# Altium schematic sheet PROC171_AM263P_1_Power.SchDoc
size 431 x 279 mm; Date: Not shown in title block; ApprovedBy: Not shown in title block; CheckedBy: Not shown in title block; Author: Not shown in title block; CompanyName: Not shown in title block; Engineer: Not shown in title block; Organization: Not shown in title block; Address1: Not shown in title block; Address2: Not shown in title block; Address3: Not shown in title block; Address4: Not shown in title block; DocumentNumber: 4; Revision: Use project parameter SCH_Rev; SheetNumber: 4; SheetTotal: 26; PageSetup: Record=PageOptions¦CenterHorizontal=True¦CenterVertical=True¦PrintScale=1.00¦XCorrection=1.00¦YCorrection=1.00¦PrintKind=0¦BorderSize=5000000¦LeftOffset=0¦BottomOffset=0¦Orientation=2¦PaperLength=1000¦PaperWidth=1000¦Scale=100¦PaperSource=15¦PrintQuality=600¦MediaType=1¦DitherType=10¦PaperKind=Letter¦PrintScaleMode=1
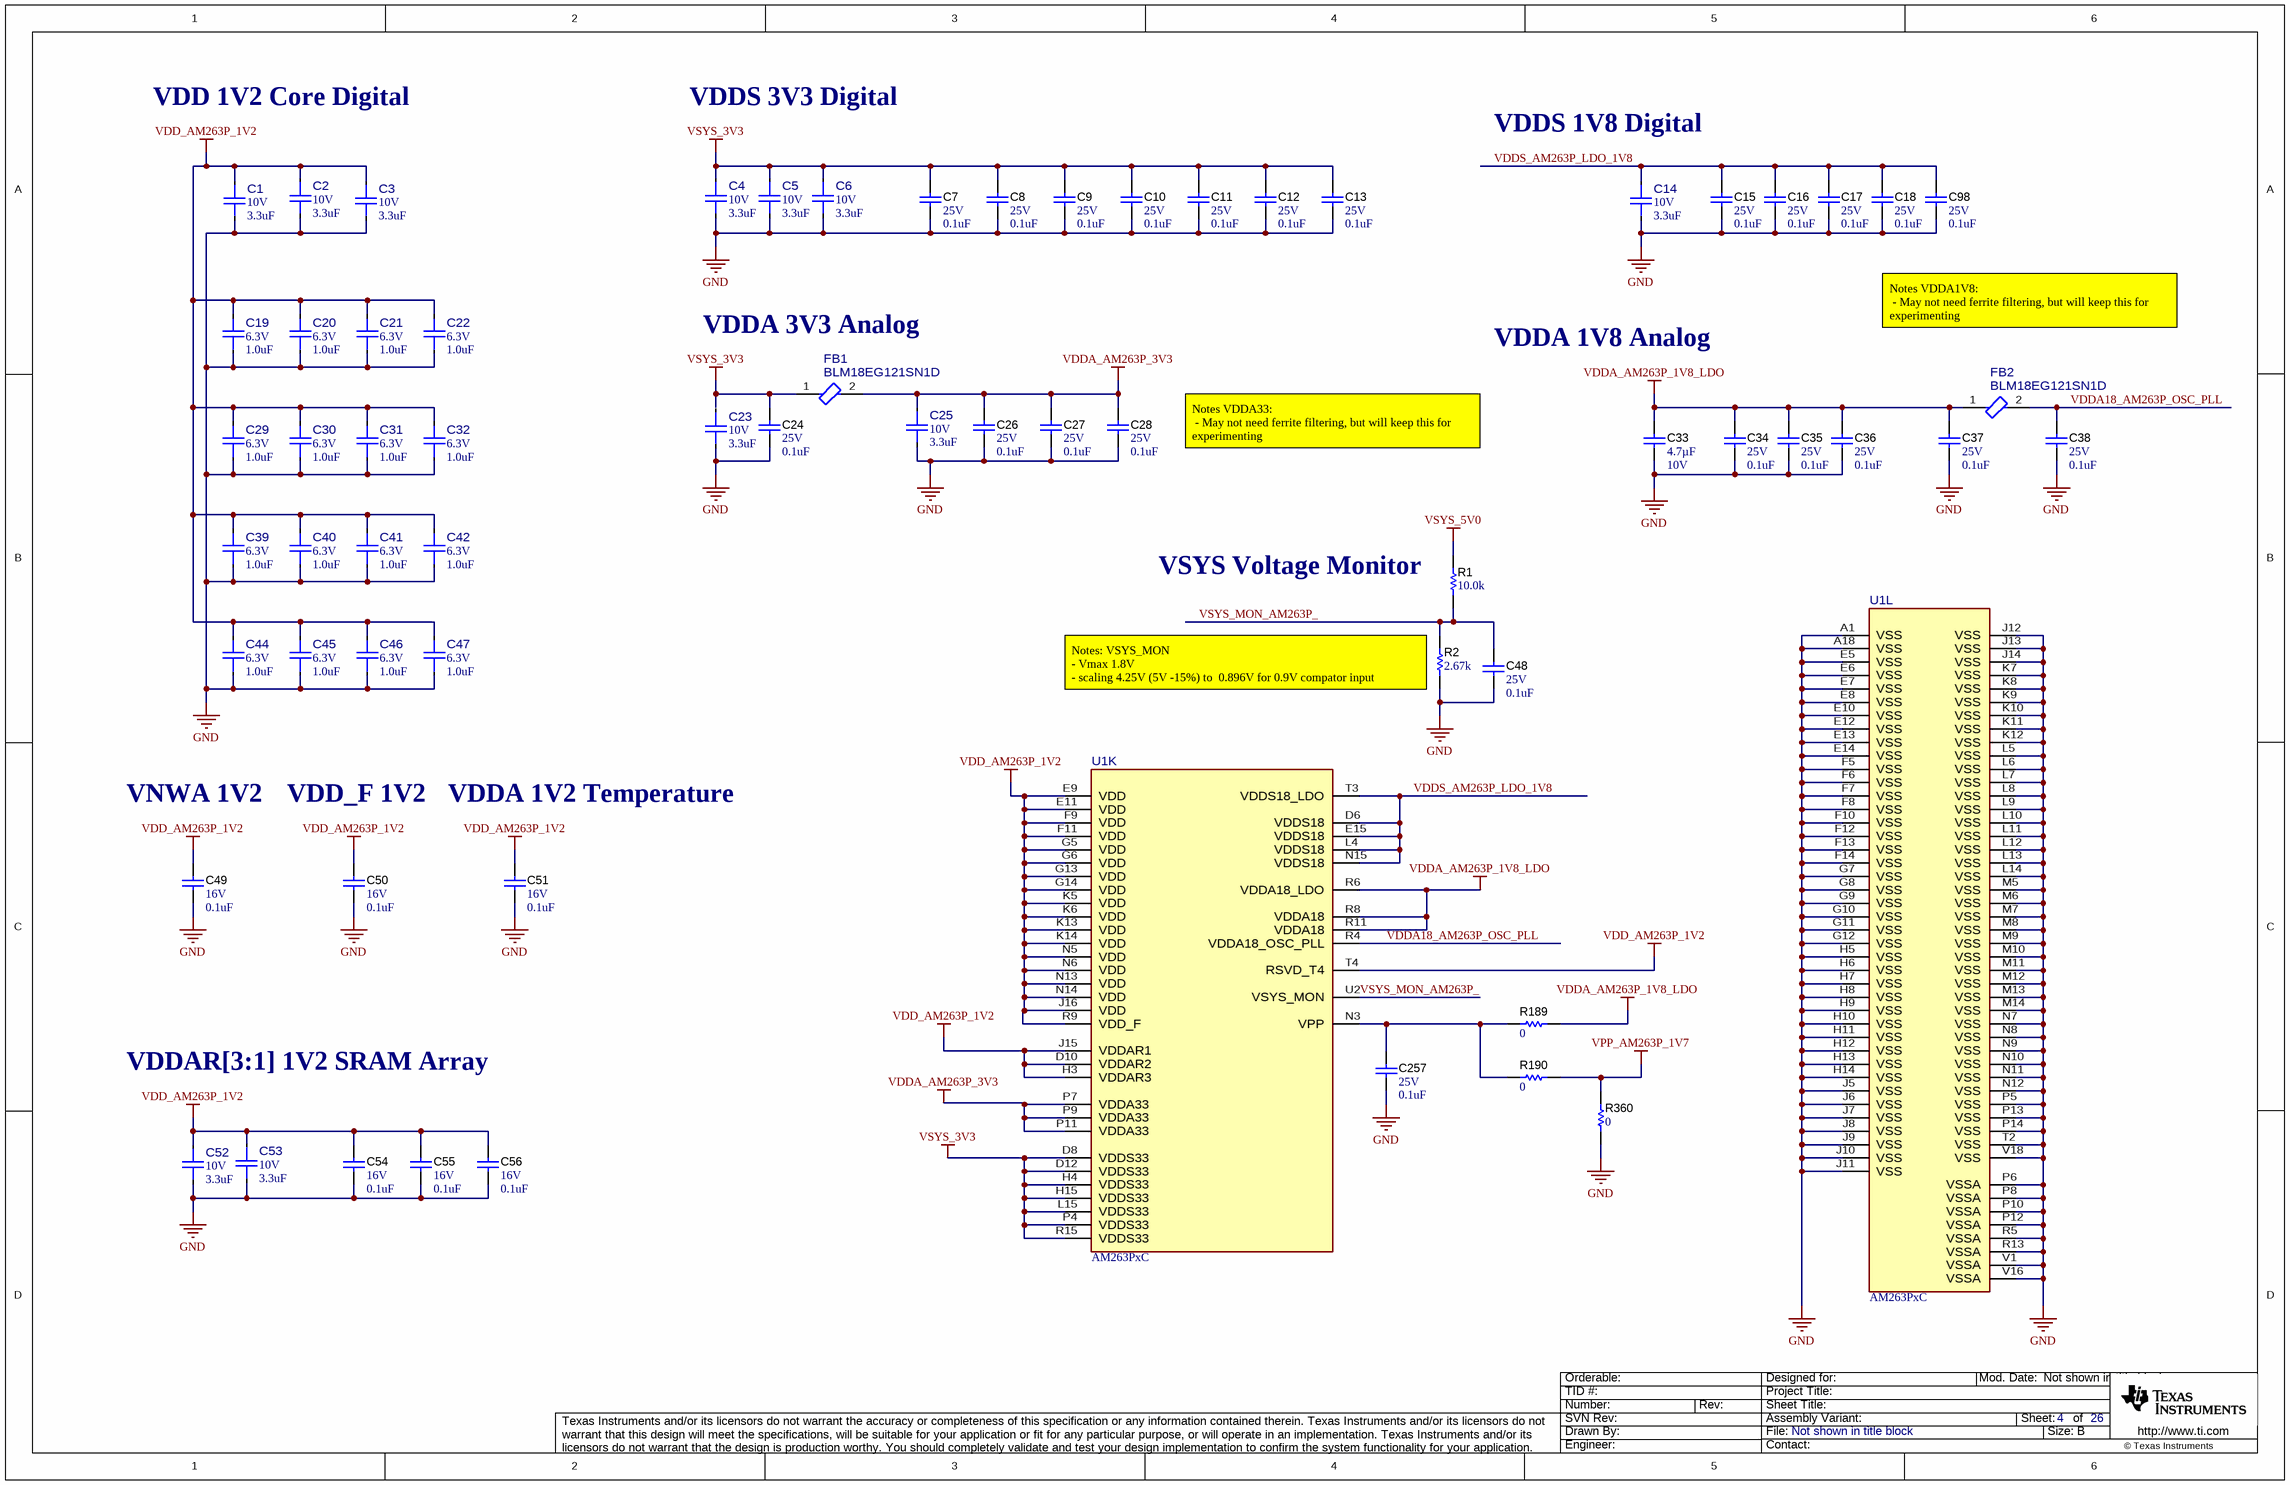
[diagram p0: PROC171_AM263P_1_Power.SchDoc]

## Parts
C1  VDC_V: 10V  ValueDisplayed: 3.3uF  [FP-CL10A335KP8NNNC_0603-MFG]  (hidden comment: CL10A335KP8NNNC)
C2  VDC_V: 10V  ValueDisplayed: 3.3uF  [FP-CL10A335KP8NNNC_0603-MFG]  (hidden comment: CL10A335KP8NNNC)
C3  VDC_V: 10V  ValueDisplayed: 3.3uF  [FP-CL10A335KP8NNNC_0603-MFG]  (hidden comment: CL10A335KP8NNNC)
C4  VDC_V: 10V  ValueDisplayed: 3.3uF  [FP-CL10A335KP8NNNC_0603-MFG]  (hidden comment: CL10A335KP8NNNC)
C5  VDC_V: 10V  ValueDisplayed: 3.3uF  [FP-CL10A335KP8NNNC_0603-MFG]  (hidden comment: CL10A335KP8NNNC)
C6  VDC_V: 10V  ValueDisplayed: 3.3uF  [FP-CL10A335KP8NNNC_0603-MFG]  (hidden comment: CL10A335KP8NNNC)
C7  VDC_V: 25V  ValueDisplayed: 0.1uF  [0402]  (hidden comment: GRM155R71E104KE14D)
C8  VDC_V: 25V  ValueDisplayed: 0.1uF  [0402]  (hidden comment: GRM155R71E104KE14D)
C9  VDC_V: 25V  ValueDisplayed: 0.1uF  [0402]  (hidden comment: GRM155R71E104KE14D)
C10  VDC_V: 25V  ValueDisplayed: 0.1uF  [0402]  (hidden comment: GRM155R71E104KE14D)
C11  VDC_V: 25V  ValueDisplayed: 0.1uF  [0402]  (hidden comment: GRM155R71E104KE14D)
C12  VDC_V: 25V  ValueDisplayed: 0.1uF  [0402]  (hidden comment: GRM155R71E104KE14D)
C13  VDC_V: 25V  ValueDisplayed: 0.1uF  [0402]  (hidden comment: GRM155R71E104KE14D)
C14  VDC_V: 10V  ValueDisplayed: 3.3uF  [FP-CL10A335KP8NNNC_0603-MFG]  (hidden comment: CL10A335KP8NNNC)
C15  VDC_V: 25V  ValueDisplayed: 0.1uF  [0402]  (hidden comment: GRM155R71E104KE14D)
C16  VDC_V: 25V  ValueDisplayed: 0.1uF  [0402]  (hidden comment: GRM155R71E104KE14D)
C17  VDC_V: 25V  ValueDisplayed: 0.1uF  [0402]  (hidden comment: GRM155R71E104KE14D)
C18  VDC_V: 25V  ValueDisplayed: 0.1uF  [0402]  (hidden comment: GRM155R71E104KE14D)
C19  VDC_V: 6.3V  ValueDisplayed: 1.0uF  [FP-GRM033C80J105ME05D_0201-MFG]  (hidden comment: GRM033C80J105ME05D)
C20  VDC_V: 6.3V  ValueDisplayed: 1.0uF  [FP-GRM033C80J105ME05D_0201-MFG]  (hidden comment: GRM033C80J105ME05D)
C21  VDC_V: 6.3V  ValueDisplayed: 1.0uF  [FP-GRM033C80J105ME05D_0201-MFG]  (hidden comment: GRM033C80J105ME05D)
C22  VDC_V: 6.3V  ValueDisplayed: 1.0uF  [FP-GRM033C80J105ME05D_0201-MFG]  (hidden comment: GRM033C80J105ME05D)
C23  VDC_V: 10V  ValueDisplayed: 3.3uF  [FP-CL10A335KP8NNNC_0603-MFG]  (hidden comment: CL10A335KP8NNNC)
C24  VDC_V: 25V  ValueDisplayed: 0.1uF  [0402]  (hidden comment: GRM155R71E104KE14D)
C25  VDC_V: 10V  ValueDisplayed: 3.3uF  [FP-CL10A335KP8NNNC_0603-MFG]  (hidden comment: CL10A335KP8NNNC)
C26  VDC_V: 25V  ValueDisplayed: 0.1uF  [0402]  (hidden comment: GRM155R71E104KE14D)
C27  VDC_V: 25V  ValueDisplayed: 0.1uF  [0402]  (hidden comment: GRM155R71E104KE14D)
C28  VDC_V: 25V  ValueDisplayed: 0.1uF  [0402]  (hidden comment: GRM155R71E104KE14D)
C29  VDC_V: 6.3V  ValueDisplayed: 1.0uF  [FP-GRM033C80J105ME05D_0201-MFG]  (hidden comment: GRM033C80J105ME05D)
C30  VDC_V: 6.3V  ValueDisplayed: 1.0uF  [FP-GRM033C80J105ME05D_0201-MFG]  (hidden comment: GRM033C80J105ME05D)
C31  VDC_V: 6.3V  ValueDisplayed: 1.0uF  [FP-GRM033C80J105ME05D_0201-MFG]  (hidden comment: GRM033C80J105ME05D)
C32  VDC_V: 6.3V  ValueDisplayed: 1.0uF  [FP-GRM033C80J105ME05D_0201-MFG]  (hidden comment: GRM033C80J105ME05D)
C33  Cap_F: 4.7µF  VDC_V: 10V  [0603]  (hidden comment: GRM188Z71A475ME15D)
C34  VDC_V: 25V  ValueDisplayed: 0.1uF  [0402]  (hidden comment: GRM155R71E104KE14D)
C35  VDC_V: 25V  ValueDisplayed: 0.1uF  [0402]  (hidden comment: GRM155R71E104KE14D)
C36  VDC_V: 25V  ValueDisplayed: 0.1uF  [0402]  (hidden comment: GRM155R71E104KE14D)
C37  VDC_V: 25V  ValueDisplayed: 0.1uF  [0402]  (hidden comment: GRM155R71E104KE14D)
C38  VDC_V: 25V  ValueDisplayed: 0.1uF  [0402]  (hidden comment: GRM155R71E104KE14D)
C39  VDC_V: 6.3V  ValueDisplayed: 1.0uF  [FP-GRM033C80J105ME05D_0201-MFG]  (hidden comment: GRM033C80J105ME05D)
C40  VDC_V: 6.3V  ValueDisplayed: 1.0uF  [FP-GRM033C80J105ME05D_0201-MFG]  (hidden comment: GRM033C80J105ME05D)
C41  VDC_V: 6.3V  ValueDisplayed: 1.0uF  [FP-GRM033C80J105ME05D_0201-MFG]  (hidden comment: GRM033C80J105ME05D)
C42  VDC_V: 6.3V  ValueDisplayed: 1.0uF  [FP-GRM033C80J105ME05D_0201-MFG]  (hidden comment: GRM033C80J105ME05D)
C44  VDC_V: 6.3V  ValueDisplayed: 1.0uF  [FP-GRM033C80J105ME05D_0201-MFG]  (hidden comment: GRM033C80J105ME05D)
C45  VDC_V: 6.3V  ValueDisplayed: 1.0uF  [FP-GRM033C80J105ME05D_0201-MFG]  (hidden comment: GRM033C80J105ME05D)
C46  VDC_V: 6.3V  ValueDisplayed: 1.0uF  [FP-GRM033C80J105ME05D_0201-MFG]  (hidden comment: GRM033C80J105ME05D)
C47  VDC_V: 6.3V  ValueDisplayed: 1.0uF  [FP-GRM033C80J105ME05D_0201-MFG]  (hidden comment: GRM033C80J105ME05D)
C48  VDC_V: 25V  ValueDisplayed: 0.1uF  [0402]  (hidden comment: GRM155R71E104KE14D)
C49  VDC_V: 16V  ValueDisplayed: 0.1uF  [0201]  (hidden comment: GRM033Z71C104KE14D)
C50  VDC_V: 16V  ValueDisplayed: 0.1uF  [0201]  (hidden comment: GRM033Z71C104KE14D)
C51  VDC_V: 16V  ValueDisplayed: 0.1uF  [0201]  (hidden comment: GRM033Z71C104KE14D)
C52  VDC_V: 10V  ValueDisplayed: 3.3uF  [FP-CL10A335KP8NNNC_0603-MFG]  (hidden comment: CL10A335KP8NNNC)
C53  VDC_V: 10V  ValueDisplayed: 3.3uF  [FP-CL10A335KP8NNNC_0603-MFG]  (hidden comment: CL10A335KP8NNNC)
C54  VDC_V: 16V  ValueDisplayed: 0.1uF  [0201]  (hidden comment: GRM033Z71C104KE14D)
C55  VDC_V: 16V  ValueDisplayed: 0.1uF  [0201]  (hidden comment: GRM033Z71C104KE14D)
C56  VDC_V: 16V  ValueDisplayed: 0.1uF  [0201]  (hidden comment: GRM033Z71C104KE14D)
C98  VDC_V: 25V  ValueDisplayed: 0.1uF  [0402]  (hidden comment: GRM155R71E104KE14D)
C257  VDC_V: 25V  ValueDisplayed: 0.1uF  [0402]  (hidden comment: GRM155R71E104KE14D)
FB1  BLM18EG121SN1D  [FP-BLM18EG121SN1D_0603-MFG]
FB2  BLM18EG121SN1D  [FP-BLM18EG121SN1D_0603-MFG]
R1  ValueDisplayed: 10.0k  [0402]  (hidden comment: ERJ-2RKF1002X)
R2  ValueDisplayed: 2.67k  [0402]  (hidden comment: CRCW04022K67FKED)
R189  value 0  [0402L]  (hidden comment: ERJ-2GE0R00X)
R190  value 0  [0402L]  (hidden comment: ERJ-2GE0R00X)
R360  value 0  [0402L]  (hidden comment: ERJ-2GE0R00X)
U1  AM263PxC  [ZCZ0324A-MFG]  (parts K,L of 13)

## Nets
GND: C1.2 C2.2 C3.2 C4.2 C5.2 C6.2 C7.2 C8.2 C9.2 C10.2 C11.2 C12.2 C13.2 C14.2 C15.2 C16.2 C17.2 C18.2 C19.1 C20.1 C21.1 C22.1 C23.2 C24.2 C25.2 C26.2 C27.2 C28.2 C29.1 C30.1 C31.1 C32.1 C33.2 C34.2 C35.2 C36.2 C37.2 C38.2 C39.1 C40.1 C41.1 C42.1 C44.1 C45.1 C46.1 C47.1 C48.2 C49.2 C50.2 C51.2 C52.2 C53.2 C54.2 C55.2 C56.2 C98.2 C257.2 R2.1 R360.1 U1.A1(VSS) U1.A18(VSS) U1.E5(VSS) U1.E6(VSS) U1.E7(VSS) U1.E8(VSS) U1.E10(VSS) U1.E12(VSS) U1.E13(VSS) U1.E14(VSS) U1.F5(VSS) U1.F6(VSS) U1.F7(VSS) U1.F8(VSS) U1.F10(VSS) U1.F12(VSS) U1.F13(VSS) U1.F14(VSS) U1.G7(VSS) U1.G8(VSS) U1.G9(VSS) U1.G10(VSS) U1.G11(VSS) U1.G12(VSS) U1.H5(VSS) U1.H6(VSS) U1.H7(VSS) U1.H8(VSS) U1.H9(VSS) U1.H10(VSS) U1.H11(VSS) U1.H12(VSS) U1.H13(VSS) U1.H14(VSS) U1.J5(VSS) U1.J6(VSS) U1.J7(VSS) U1.J8(VSS) U1.J9(VSS) U1.J10(VSS) U1.J11(VSS) U1.J12(VSS) U1.J13(VSS) U1.J14(VSS) U1.K7(VSS) U1.K8(VSS) U1.K9(VSS) U1.K10(VSS) U1.K11(VSS) U1.K12(VSS) U1.L5(VSS) U1.L6(VSS) U1.L7(VSS) U1.L8(VSS) U1.L9(VSS) U1.L10(VSS) U1.L11(VSS) U1.L12(VSS) U1.L13(VSS) U1.L14(VSS) U1.M5(VSS) U1.M6(VSS) U1.M7(VSS) U1.M8(VSS) U1.M9(VSS) U1.M10(VSS) U1.M11(VSS) U1.M12(VSS) U1.M13(VSS) U1.M14(VSS) U1.N7(VSS) U1.N8(VSS) U1.N9(VSS) U1.N10(VSS) U1.N11(VSS) U1.N12(VSS) U1.P5(VSS) U1.P6(VSSA) U1.P8(VSSA) U1.P10(VSSA) U1.P12(VSSA) U1.P13(VSS) U1.P14(VSS) U1.R5(VSSA) U1.R13(VSSA) U1.T2(VSS) U1.V1(VSSA) U1.V16(VSSA) U1.V18(VSS)
VDD_AM263P_1V2: C1.1 C2.1 C3.1 C19.2 C20.2 C21.2 C22.2 C29.2 C30.2 C31.2 C32.2 C39.2 C40.2 C41.2 C42.2 C44.2 C45.2 C46.2 C47.2 C49.1 C50.1 C51.1 C52.1 C53.1 C54.1 C55.1 C56.1 U1.D10(VDDAR2) U1.E9(VDD) U1.E11(VDD) U1.F9(VDD) U1.F11(VDD) U1.G5(VDD) U1.G6(VDD) U1.G13(VDD) U1.G14(VDD) U1.H3(VDDAR3) U1.J15(VDDAR1) U1.J16(VDD) U1.K5(VDD) U1.K6(VDD) U1.K13(VDD) U1.K14(VDD) U1.N5(VDD) U1.N6(VDD) U1.N13(VDD) U1.N14(VDD) U1.R9(VDD_F) U1.T4(RSVD_T4)
VDDA_AM263P_1V8_LDO: C33.1 C34.1 C35.1 C36.1 C37.1 FB2.1 R189.2 U1.R6(VDDA18_LDO) U1.R8(VDDA18) U1.R11(VDDA18)
VDDA_AM263P_3V3: C25.1 C26.1 C27.1 C28.1 FB1.2 U1.P7(VDDA33) U1.P9(VDDA33) U1.P11(VDDA33)
VPP_AM263P_1V7: R190.2 R360.2
VSYS_3V3: C4.1 C5.1 C6.1 C7.1 C8.1 C9.1 C10.1 C11.1 C12.1 C13.1 C24.1 FB1.1 U1.D8(VDDS33) U1.D12(VDDS33) U1.H4(VDDS33) U1.H15(VDDS33) U1.L15(VDDS33) U1.P4(VDDS33) U1.R15(VDDS33)
VSYS_5V0: R1.2
VDDA18_AM263P_OSC_PLL: C38.1 FB2.2 U1.R4(VDDA18_OSC_PLL)
VDDS_AM263P_LDO_1V8: C14.1 C15.1 C16.1 C17.1 C18.1 C98.1 U1.D6(VDDS18) U1.E15(VDDS18) U1.L4(VDDS18) U1.N15(VDDS18) U1.T3(VDDS18_LDO)
VSYS_MON_AM263P_: C48.1 R1.1 R2.2 U1.U2(VSYS_MON)
NetC257_1: C257.1 R189.1 R190.1 U1.N3(VPP)

Not connected (* = marked no-connect by the designer): C23 1

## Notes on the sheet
- VDD 1V2 Core Digital
- VDDS 3V3 Digital
- VDDS 1V8 Digital
- VDDA 3V3 Analog
- VDDA 1V8 Analog
- Notes VDDA1V8:
  - May not need ferrite filtering, but will keep this for experimenting
- Notes VDDA33:
  - May not need ferrite filtering, but will keep this for experimenting
- (near R1) VSYS Voltage Monitor
- (near R2) Notes: VSYS_MON
  - Vmax 1.8V
  - scaling 4.25V (5V -15%) to  0.896V for 0.9V compator input
- VNWA 1V2
- VDD_F 1V2
- VDDA 1V2 Temperature
- VDDAR[3:1] 1V2 SRAM Array

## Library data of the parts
C1-C6 C14 C23 C25 C52 C53 = CMP-0042976-1: Cap Ceramic 3.3uF 10V X5R ±10% Pad SMD 0603 +85°C T/R; Manufacturer: Samsung; TempCo: 15%; Value: 3.3µF; SizeZ_mm: 0.9mm; AEC Qualified: No
C7-C13 C15-C18 C24 C26-C28 C34-C38 C48 C98 C257 = CMP-0006659-2: CAP, CERM, 0.1 uF, 25 V, +/- 10%, X7R, 0402; Manufacturer: MuRata; TaMin_C: -55°C; Polarized: N; SizeAreaWB_mm2: 3; Value1: Unknown; U/M: EA; Value: 0.1uF; TaMax_C: 125°C; SizeZ_mm: 0.6; SizeX_mm: 1; SizeY_mm: 0.5; Cap_F: 100nF; AEC Category: Q200
C19-C22 C29-C32 C39-C42 C44-C47 = CMP-0093721-1: Chip Multilayer Ceramic Capacitors for General Purpose, 0201, 1.0uF, X6S, 22%, 20%, 6.3V; Manufacturer: Murata; Cap_F: 1µF; Value: 1µF; AEC Qualified: No; SizeZ_mm: 0.39mm
C33 = CMP-0007498-4: CAP, CERM, 4.7 uF, 10 V, +/- 20%, X7R, 0603; Manufacturer: MuRata; TaMin_C: -55°C; Polarized: N; SizeAreaWB_mm2: 4.68; Value1: Unknown; U/M: EA; Value: 4.7uF; TaMax_C: 125°C; SizeZ_mm: 1; SizeX_mm: 1.6; SizeY_mm: 0.8; SizeArea_mm2: 1.28; AEC Category: Q200
C49-C51 C54-C56 = CMP-0064970-1: CAP, CERM, 0.1 uF, 16 V,+/- 10%, X7R, 0201; Manufacturer: MuRata; TaMin_C: -55°C; Polarized: N; SizeAreaWB_mm2: 2.08; Value1: Unknown; U/M: EA; Value: 0.1uF; TaMax_C: 125°C; SizeZ_mm: 0.26; SizeX_mm: 0.6; SizeY_mm: 0.3; SizeArea_mm2: 0.18; Cap_F: 100nF; AEC Category: Q200
FB1 FB2 = CMP-0089199-1: 120 Ohms @ 100MHz 1  Ferrite Bead 0603 (1608 Metric) 2A 40mOhm; Manufacturer: Murata; DCR_ohm: 60m; AEC Qualified: No; Tolerance_%: 25%; SizeZ_mm: 0.95mm; Impedance At Frequency: 120Ω @ 100MHz
R1 = CMP-0026658-1: RES, 10.0 k, 1%, 0.1 W, 0402; Manufacturer: Panasonic; Power_W: 100mW; TempCo: 100 ppm/C; Value_Code: 10k0; U/M: EA; Value: 10.0k; EIA_Code: E96; Res_ohm: 10k; SizeX_mm: 1; SizeY_mm: 0.5; SizeZ_mm: 0.6; Value2: 0.1W; VDC_V: 50V; AEC Category: Q200
R2 = CMP-0026240-2: RES, 2.67 k, 1%, 0.063 W, AEC-Q200 Grade 0, 0402; Manufacturer: Vishay-Dale; Power_W: 63mW; TempCo: 100 ppm/C; Value_Code: 2k67; Value: 2.67k; EIA_Code: E96; SizeX_mm: 1; SizeY_mm: 0.5; SizeZ_mm: 0.6; Value2: 0.063W; AEC Qualified: Y; VDC_V: 50V; AEC Category: Q200; AEC Grade: 0
R189 R190 R360 = CMP-0026992-3: RES, 0, 5%, 0.1 W, AEC-Q200 Grade 0, 0402; Manufacturer: Panasonic; Power_W: 100mW; TempCo: 600 ppm/C; Value_Code: 0000; EIA_Code: E24; SizeX_mm: 1; SizeY_mm: 0.5; SizeZ_mm: 0.6; Value2: 0.1W; AEC Qualified: Y; VDC_V: 50V; AEC Category: Q200; SizeAreaWB_mm2: 3
U1 = CMP-0001698-2: Sitara™ Microcontroller; Manufacturer: Texas Instruments; SizeZ_mm: 1.4mm; Core Architecture: ARM Cortex-R5F; Data Bus Width: 32bits; Frequency_Fixed: 200MHz; Interface: I2C,SPI,UART,CAN,LIN,Ethernet,Other; Max Supply Voltage: 3.465V; Memory Size: 2MBytes; Memory Type: RAM; Min Supply Voltage: 1.14V; Number Of Cores: 1; Number Of I/Os: 140; Number Of I2C Channels: 4; Number Of Spi Channels: 5; Number Of Uart Channels: 6; Standoff Height: 0.35mm; AEC Category: Q200; CompType: IC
